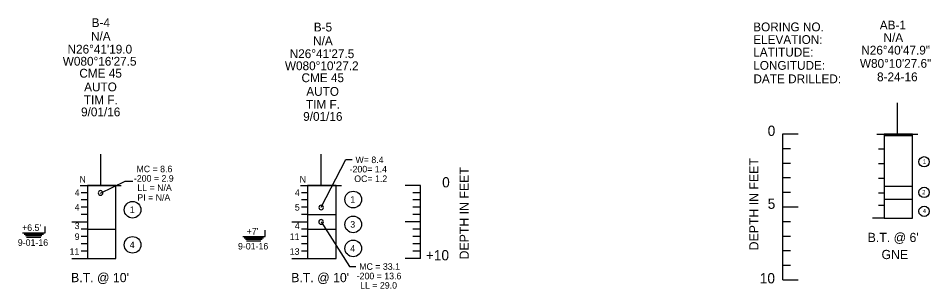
# Model space of a CAD drawing. Extents: x 0 to 331, y -72 to 117.
# Drawn here: x 47.19 to 80.68, y 22.64 to 32.57 of the extents above; entities that cross this region are included whole.
import ezdxf

# ---------------------------------------------------------------- set-up
doc = ezdxf.new("R2010")
doc.units = 0
for name, color, linetype in [('1-BORE', 7, 'Continuous'), ('1-GRID', 7, 'Continuous'), ('1-TEXT', 7, 'Continuous')]:
    doc.layers.add(name, color=color, linetype=linetype)

msp = doc.modelspace()

# ---------------------------------------------------------------- linework, layer by layer
at = {"layer": '1-BORE'}
for p, q in [((78.97, 28.272), (80.015, 28.272)), ((58.313, 25.634), (59.217, 27.383)), ((59.217, 27.383), (59.445, 27.383)), ((50.212, 26.157), (51.116, 26.596)), ((51.116, 26.596), (51.393, 26.596)), ((78.97, 26.413), (80.015, 26.413)), ((78.97, 26.413), (80.015, 26.413)), ((78.97, 25.927), (80.015, 25.927)), ((78.97, 25.927), (80.015, 25.927)), ((57.812, 25.366), (58.857, 25.366)), ((78.97, 25.233), (78.541, 25.233)), ((78.97, 25.233), (80.015, 25.233)), ((49.731, 24.83), (50.776, 24.83)), ((57.812, 24.83), (58.857, 24.83)), ((58.309, 25.102), (59.352, 23.465)), ((49.731, 23.759), (50.776, 23.759)), ((57.812, 23.759), (58.857, 23.759)), ((59.352, 23.465), (59.58, 23.465))]:
    msp.add_line(p, q, dxfattribs=at)
for points in [[(80.015, 28.272), (80.015, 28.313), (78.97, 28.313), (78.97, 28.272), (80.015, 28.272), (80.015, 28.272)], [(80.015, 25.233), (80.015, 28.313), (78.97, 28.313), (78.97, 25.233)], [(50.776, 23.759), (50.776, 26.438), (49.731, 26.438), (49.731, 23.759)], [(58.857, 23.759), (58.857, 26.438), (57.812, 26.438), (57.812, 23.759)]]:
    msp.add_lwpolyline(points, dxfattribs=at)
for centre, start, end in [((50.213, 26.159), 0, 180), ((50.213, 26.159), 180, 0), ((58.31, 25.627), 0, 180), ((58.31, 25.627), 180, 0), ((58.306, 25.095), 0, 180), ((58.306, 25.095), 180, 0)]:
    msp.add_arc(centre, 0.0848, start, end, dxfattribs=at)
at = {"layer": '1-GRID'}
for p, q in [((75.254, 28.329), (75.819, 28.329)), ((75.254, 27.793), (75.539, 27.793)), ((78.765, 27.777), (78.97, 27.777)), ((75.254, 27.257), (75.539, 27.257)), ((78.765, 27.242), (78.97, 27.242)), ((75.254, 26.721), (75.539, 26.721)), ((78.765, 26.706), (78.97, 26.706)), ((61.954, 26.438), (61.39, 26.438)), ((61.954, 26.17), (61.669, 26.17)), ((75.254, 26.185), (75.539, 26.185)), ((78.765, 26.17), (78.97, 26.17)), ((61.954, 25.902), (61.669, 25.902)), ((61.954, 25.634), (61.669, 25.634)), ((75.254, 25.649), (75.819, 25.649)), ((75.254, 25.649), (75.819, 25.649)), ((78.765, 25.707), (78.97, 25.707)), ((61.954, 25.366), (61.669, 25.366)), ((78.97, 25.233), (79.174, 25.233)), ((61.954, 25.098), (61.39, 25.098)), ((61.954, 25.098), (61.39, 25.098)), ((61.954, 24.83), (61.669, 24.83)), ((75.254, 25.113), (75.539, 25.113)), ((61.954, 24.563), (61.669, 24.563)), ((75.254, 24.578), (75.539, 24.578)), ((61.954, 24.295), (61.669, 24.295)), ((61.954, 24.027), (61.669, 24.027)), ((75.254, 24.042), (75.539, 24.042)), ((61.954, 23.759), (61.39, 23.759)), ((75.254, 23.506), (75.539, 23.506)), ((75.254, 22.97), (75.819, 22.97))]:
    msp.add_line(p, q, dxfattribs=at)
for points in [[(75.254, 25.649), (75.254, 28.329)], [(61.954, 23.759), (61.954, 26.438)], [(75.254, 22.97), (75.254, 25.649)]]:
    msp.add_lwpolyline(points, dxfattribs=at)
at = {"layer": '1-TEXT'}
for p, q in [((79.449, 29.464), (79.449, 28.313)), ((50.211, 27.589), (50.211, 26.438)), ((58.292, 27.589), (58.292, 26.438)), ((49.731, 26.17), (49.502, 26.17)), ((57.812, 26.17), (57.583, 26.17)), ((49.731, 25.902), (49.502, 25.902)), ((57.812, 25.902), (57.583, 25.902)), ((49.731, 25.634), (49.502, 25.634)), ((57.812, 25.634), (57.583, 25.634)), ((49.731, 25.366), (49.502, 25.366)), ((57.812, 25.366), (57.583, 25.366)), ((48.178, 24.697), (48.178, 24.932)), ((49.158, 25.098), (49.731, 25.098)), ((49.731, 24.83), (49.502, 24.83)), ((56.259, 24.563), (56.259, 24.798)), ((57.239, 25.098), (57.812, 25.098)), ((57.812, 24.83), (57.583, 24.83)), ((47.353, 24.697), (48.178, 24.697)), ((47.407, 24.648), (48.117, 24.648)), ((47.454, 24.599), (48.061, 24.599)), ((47.493, 24.54), (48.017, 24.54)), ((49.731, 24.563), (49.502, 24.563)), ((55.433, 24.563), (56.259, 24.563)), ((55.488, 24.514), (56.198, 24.514)), ((55.535, 24.465), (56.141, 24.465)), ((57.812, 24.563), (57.583, 24.563)), ((49.731, 24.295), (49.502, 24.295)), ((55.574, 24.406), (56.098, 24.406)), ((57.812, 24.295), (57.583, 24.295)), ((49.731, 24.027), (49.502, 24.027)), ((57.812, 24.027), (57.583, 24.027)), ((49.158, 23.759), (49.731, 23.759)), ((57.239, 23.759), (57.812, 23.759))]:
    msp.add_line(p, q, dxfattribs=at)
for points in [[(78.703, 28.313), (80.212, 28.313)], [(49.465, 26.438), (50.974, 26.438)], [(57.546, 26.438), (59.055, 26.438)]]:
    msp.add_lwpolyline(points, dxfattribs=at)
for centre, radius in [((80.438, 27.303), 0.19), ((59.486, 25.918), 0.305), ((80.438, 26.182), 0.19), ((51.39, 25.542), 0.305), ((80.438, 25.485), 0.19), ((59.486, 25.006), 0.305), ((51.39, 24.255), 0.305), ((59.486, 24.124), 0.305)]:
    msp.add_circle(centre, radius, dxfattribs=at)

# ---------------------------------------------------------------- texts
at = {"layer": '1-GRID'}
for s, height, p in [('0', 0.375, (74.699, 28.256)), ('0', 0.375, (62.75, 26.365)), ('5', 0.375, (74.699, 25.576)), ('+10', 0.3751, (62.152, 23.686)), ('10', 0.3751, (74.408, 22.84))]:
    msp.add_text(s, height=height, dxfattribs=at).set_placement(p)
for p in [(74.361, 24.052), (63.728, 23.719)]:
    msp.add_text('DEPTH IN FEET', height=0.3376, rotation=90, dxfattribs=at).set_placement(p)
at = {"layer": '1-TEXT'}
for s, height, p in [('B-4', 0.3231, (49.886, 32.251)), ('B-5', 0.3231, (58.039, 32.089)), ('BORING NO.', 0.3231, (74.168, 32.095)), ('AB-1', 0.3231, (78.813, 32.164)), ('N/A', 0.3231, (49.861, 31.75)), ('N/A', 0.3231, (58.014, 31.583)), ('ELEVATION:', 0.3231, (74.168, 31.63)), ('N/A', 0.3231, (78.951, 31.701)), ("N26°41'19.0", 0.32313, (49.001, 31.277)), ('LATITUDE:', 0.3231, (74.168, 31.168)), ('N26%%D40\'47.9"', 0.32313, (78.134, 31.241)), ("W080°16'27.5", 0.32313, (48.826, 30.833)), ("N26°41'27.5", 0.32313, (57.155, 31.111)), ("W080°10'27.2", 0.32313, (56.979, 30.667)), ('LONGITUDE:', 0.3231, (74.168, 30.682)), ('W80%%D10\'27.6"', 0.32313, (78.084, 30.755)), ('CME 45', 0.3231, (49.434, 30.394)), ('CME 45', 0.3231, (57.588, 30.228)), ('DATE DRILLED:', 0.32313, (74.176, 30.188)), ('8-24-16', 0.3231, (78.713, 30.261)), ('AUTO', 0.3231, (49.61, 29.892)), ('AUTO', 0.3231, (57.764, 29.726)), ('TIM F.', 0.3231, (49.598, 29.417)), ('TIM F.', 0.3231, (57.751, 29.251)), ('9/01/16', 0.3231, (49.496, 28.973)), ('9/01/16', 0.3231, (57.65, 28.807)), ('W= 8.4', 0.2411, (59.57, 27.256)), ('MC = 8.6', 0.2411, (51.531, 26.921)), ('-200= 1.4', 0.2411, (59.354, 26.913)), ('1', 0.152, (80.393, 27.241)), ('-200 = 2.9', 0.2411, (51.436, 26.573)), ('OC= 1.2', 0.2411, (59.524, 26.56)), ('N', 0.241, (49.44, 26.54)), ('LL = N/A', 0.2411, (51.563, 26.229)), ('N', 0.241, (57.521, 26.54)), ('4', 0.241, (49.263, 26.049)), ('PI = N/A', 0.2411, (51.563, 25.872)), ('4', 0.241, (57.344, 26.049)), ('2', 0.152, (80.37, 26.114)), ('1', 0.241, (59.379, 25.799)), ('4', 0.241, (49.263, 25.513)), ('1', 0.241, (51.283, 25.422)), ('5', 0.241, (57.344, 25.513)), ('4', 0.152, (80.393, 25.422)), ('3', 0.241, (59.379, 24.886)), ("+6.5'", 0.2411, (47.332, 24.764)), ('3', 0.241, (49.263, 24.832)), ("+7'", 0.2411, (55.576, 24.63)), ('4', 0.241, (57.344, 24.832)), ('9-01-16', 0.2411, (47.176, 24.218)), ('9', 0.241, (49.263, 24.433)), ('11', 0.2411, (57.157, 24.433)), ("B.T. @ 6'", 0.3376, (78.368, 24.358)), ('11', 0.2411, (49.076, 23.888)), ('4', 0.241, (51.283, 24.135)), ('9-01-16', 0.2411, (55.257, 24.084)), ('13', 0.2411, (57.157, 23.888)), ('4', 0.241, (59.379, 24.004)), ('GNE', 0.3376, (78.877, 23.731)), ('MC = 33.1', 0.2411, (59.707, 23.337)), ("B.T. @ 10'", 0.3376, (49.129, 22.884)), ("B.T. @ 10'", 0.3376, (57.21, 22.884)), ('-200 = 13.6', 0.24114, (59.613, 22.989)), ('LL = 29.0', 0.2411, (59.74, 22.646))]:
    msp.add_text(s, height=height, dxfattribs=at).set_placement(p)

doc.saveas('drawing.dxf')
